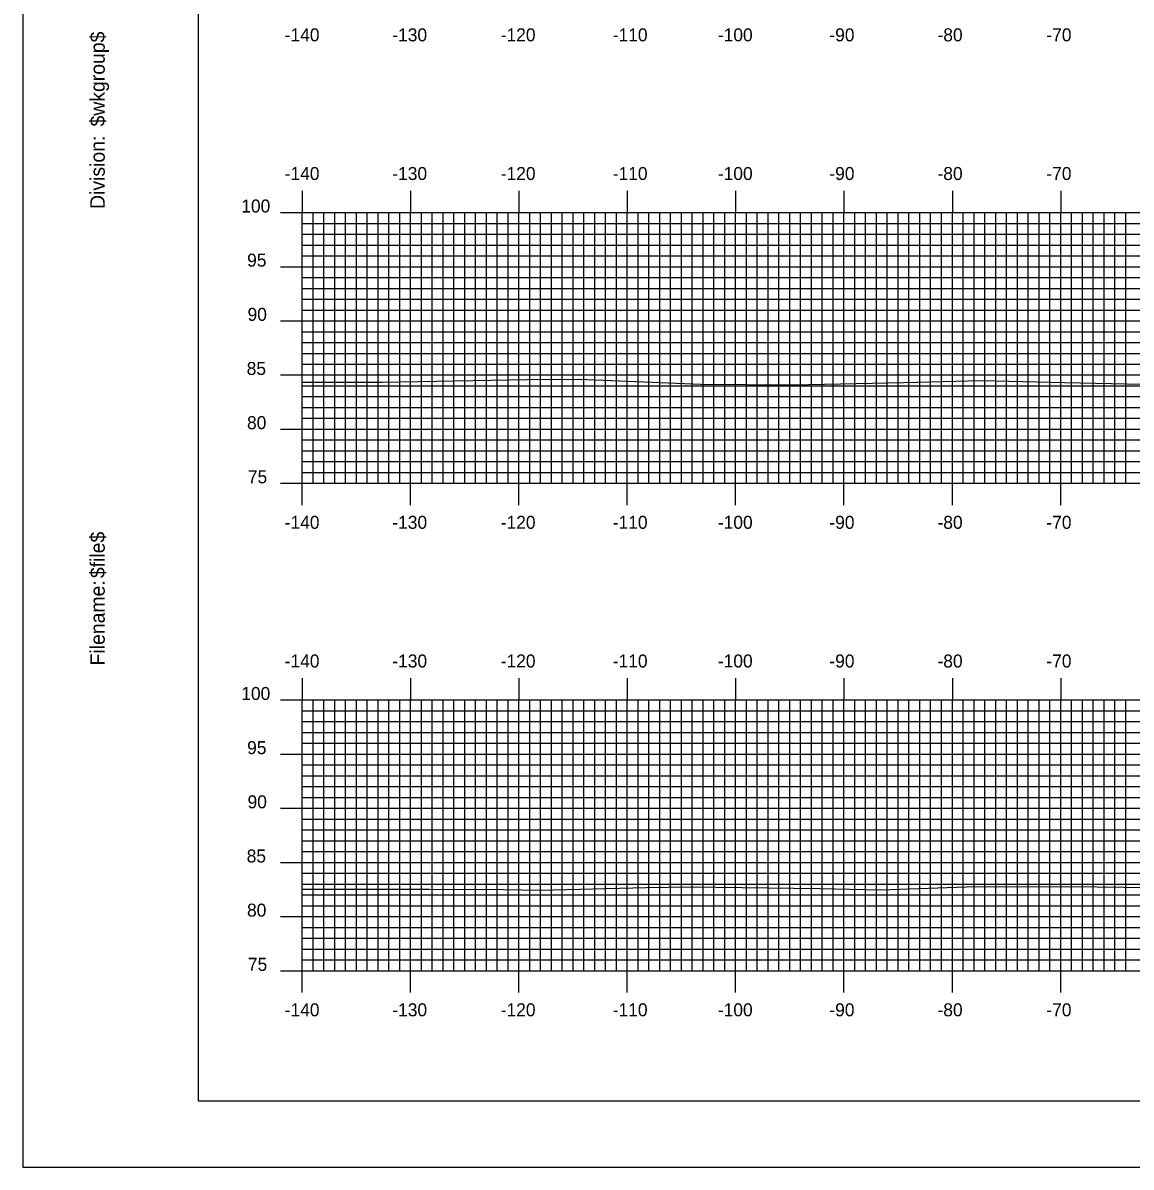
# Model space of a CAD drawing. Extents: x 854116 to 854460, y 364366 to 364586.
# Drawn here: x 854116.4 to 854218.7, y 364365.7 to 364471.3 of the extents above; entities that cross this region are included whole.
import ezdxf

# ---------------------------------------------------------------- set-up
doc = ezdxf.new("R2010")
doc.units = 0
for name, color, linetype in [('BORDER', 7, 'Continuous'), ('H_V ANNOTATION', 7, 'Continuous'), ('MAJOR', 7, 'Continuous'), ('MINOR', 7, 'Continuous'), ('PLOT BOUNDARY', 7, 'Continuous'), ('S_Roadway_Centerline', 7, 'Continuous')]:
    doc.layers.add(name, color=color, linetype=linetype)

msp = doc.modelspace()

# ---------------------------------------------------------------- linework, layer by layer
at = {"layer": 'BORDER'}
msp.add_lwpolyline([(854132.63, 364371.79), (854452.63, 364371.79), (854452.63, 364581.79), (854132.63, 364581.79)], close=True, dxfattribs=at)
at = {"layer": 'MAJOR'}
for p, q in [((854142.23, 364455.79), (854142.23, 364453.79)), ((854152.23, 364455.79), (854152.23, 364453.79)), ((854162.23, 364455.79), (854162.23, 364453.79)), ((854172.23, 364455.79), (854172.23, 364453.79)), ((854182.23, 364455.79), (854182.23, 364453.79)), ((854192.23, 364455.79), (854192.23, 364453.79)), ((854202.23, 364455.79), (854202.23, 364453.79)), ((854212.23, 364455.79), (854212.23, 364453.79)), ((854140.23, 364453.79), (854142.23, 364453.79)), ((854142.23, 364453.79), (854422.23, 364453.79)), ((854142.23, 364428.79), (854142.23, 364453.79)), ((854142.23, 364428.79), (854142.23, 364453.79)), ((854142.23, 364453.79), (854422.23, 364453.79)), ((854152.23, 364428.79), (854152.23, 364453.79)), ((854162.23, 364428.79), (854162.23, 364453.79)), ((854172.23, 364428.79), (854172.23, 364453.79)), ((854182.23, 364428.79), (854182.23, 364453.79)), ((854192.23, 364428.79), (854192.23, 364453.79)), ((854202.23, 364428.79), (854202.23, 364453.79)), ((854212.23, 364428.79), (854212.23, 364453.79)), ((854140.23, 364448.79), (854142.23, 364448.79)), ((854142.23, 364448.79), (854422.23, 364448.79)), ((854140.23, 364443.79), (854142.23, 364443.79)), ((854142.23, 364443.79), (854422.23, 364443.79)), ((854140.23, 364438.79), (854142.23, 364438.79)), ((854142.23, 364438.79), (854422.23, 364438.79)), ((854140.23, 364433.79), (854142.23, 364433.79)), ((854142.23, 364433.79), (854422.23, 364433.79)), ((854140.23, 364428.79), (854142.23, 364428.79)), ((854142.23, 364428.79), (854422.23, 364428.79)), ((854142.23, 364428.79), (854422.23, 364428.79)), ((854142.23, 364426.78), (854142.23, 364428.79)), ((854152.23, 364426.78), (854152.23, 364428.79)), ((854162.23, 364426.78), (854162.23, 364428.79)), ((854172.23, 364426.78), (854172.23, 364428.79)), ((854182.23, 364426.78), (854182.23, 364428.79)), ((854192.23, 364426.78), (854192.23, 364428.79)), ((854202.23, 364426.78), (854202.23, 364428.79)), ((854212.23, 364426.78), (854212.23, 364428.79)), ((854142.23, 364410.79), (854142.23, 364408.79)), ((854152.23, 364410.79), (854152.23, 364408.79)), ((854162.23, 364410.79), (854162.23, 364408.79)), ((854172.23, 364410.79), (854172.23, 364408.79)), ((854182.23, 364410.79), (854182.23, 364408.79)), ((854192.23, 364410.79), (854192.23, 364408.79)), ((854202.23, 364410.79), (854202.23, 364408.79)), ((854212.23, 364410.79), (854212.23, 364408.79)), ((854140.23, 364408.79), (854142.23, 364408.79)), ((854142.23, 364408.79), (854422.23, 364408.79)), ((854142.23, 364383.79), (854142.23, 364408.79)), ((854142.23, 364383.79), (854142.23, 364408.79)), ((854142.23, 364408.79), (854422.23, 364408.79)), ((854152.23, 364383.79), (854152.23, 364408.79)), ((854162.23, 364383.79), (854162.23, 364408.79)), ((854172.23, 364383.79), (854172.23, 364408.79)), ((854182.23, 364383.79), (854182.23, 364408.79)), ((854192.23, 364383.79), (854192.23, 364408.79)), ((854202.23, 364383.79), (854202.23, 364408.79)), ((854212.23, 364383.79), (854212.23, 364408.79)), ((854140.23, 364403.79), (854142.23, 364403.79)), ((854142.23, 364403.79), (854422.23, 364403.79)), ((854140.23, 364398.79), (854142.23, 364398.79)), ((854142.23, 364398.79), (854422.23, 364398.79)), ((854140.23, 364393.79), (854142.23, 364393.79)), ((854142.23, 364393.79), (854422.23, 364393.79)), ((854140.23, 364388.79), (854142.23, 364388.79)), ((854142.23, 364388.79), (854422.23, 364388.79)), ((854140.23, 364383.79), (854142.23, 364383.79)), ((854142.23, 364383.79), (854422.23, 364383.79)), ((854142.23, 364383.79), (854422.23, 364383.79)), ((854142.23, 364381.78), (854142.23, 364383.79)), ((854152.23, 364381.78), (854152.23, 364383.79)), ((854162.23, 364381.78), (854162.23, 364383.79)), ((854172.23, 364381.78), (854172.23, 364383.79)), ((854182.23, 364381.78), (854182.23, 364383.79)), ((854192.23, 364381.78), (854192.23, 364383.79)), ((854202.23, 364381.78), (854202.23, 364383.79)), ((854212.23, 364381.78), (854212.23, 364383.79))]:
    msp.add_line(p, q, dxfattribs=at)
at = {"layer": 'MINOR'}
for p, q in [((854143.23, 364428.79), (854143.23, 364453.79)), ((854144.23, 364428.79), (854144.23, 364453.79)), ((854145.23, 364428.79), (854145.23, 364453.79)), ((854146.23, 364428.79), (854146.23, 364453.79)), ((854147.23, 364428.79), (854147.23, 364453.79)), ((854148.23, 364428.79), (854148.23, 364453.79)), ((854149.23, 364428.79), (854149.23, 364453.79)), ((854150.23, 364428.79), (854150.23, 364453.79)), ((854151.23, 364428.79), (854151.23, 364453.79)), ((854153.23, 364428.79), (854153.23, 364453.79)), ((854154.23, 364428.79), (854154.23, 364453.79)), ((854155.23, 364428.79), (854155.23, 364453.79)), ((854156.23, 364428.79), (854156.23, 364453.79)), ((854157.23, 364428.79), (854157.23, 364453.79)), ((854158.23, 364428.79), (854158.23, 364453.79)), ((854159.23, 364428.79), (854159.23, 364453.79)), ((854160.23, 364428.79), (854160.23, 364453.79)), ((854161.23, 364428.79), (854161.23, 364453.79)), ((854163.23, 364428.79), (854163.23, 364453.79)), ((854164.23, 364428.79), (854164.23, 364453.79)), ((854165.23, 364428.79), (854165.23, 364453.79)), ((854166.23, 364428.79), (854166.23, 364453.79)), ((854167.23, 364428.79), (854167.23, 364453.79)), ((854168.23, 364428.79), (854168.23, 364453.79)), ((854169.23, 364428.79), (854169.23, 364453.79)), ((854170.23, 364428.79), (854170.23, 364453.79)), ((854171.23, 364428.79), (854171.23, 364453.79)), ((854173.23, 364428.79), (854173.23, 364453.79)), ((854174.23, 364428.79), (854174.23, 364453.79)), ((854175.23, 364428.79), (854175.23, 364453.79)), ((854176.23, 364428.79), (854176.23, 364453.79)), ((854177.23, 364428.79), (854177.23, 364453.79)), ((854178.23, 364428.79), (854178.23, 364453.79)), ((854179.23, 364428.79), (854179.23, 364453.79)), ((854180.23, 364428.79), (854180.23, 364453.79)), ((854181.23, 364428.79), (854181.23, 364453.79)), ((854183.23, 364428.79), (854183.23, 364453.79)), ((854184.23, 364428.79), (854184.23, 364453.79)), ((854185.23, 364428.79), (854185.23, 364453.79)), ((854186.23, 364428.79), (854186.23, 364453.79)), ((854187.23, 364428.79), (854187.23, 364453.79)), ((854188.23, 364428.79), (854188.23, 364453.79)), ((854189.23, 364428.79), (854189.23, 364453.79)), ((854190.23, 364428.79), (854190.23, 364453.79)), ((854191.23, 364428.79), (854191.23, 364453.79)), ((854193.23, 364428.79), (854193.23, 364453.79)), ((854194.23, 364428.79), (854194.23, 364453.79)), ((854195.23, 364428.79), (854195.23, 364453.79)), ((854196.23, 364428.79), (854196.23, 364453.79)), ((854197.23, 364428.79), (854197.23, 364453.79)), ((854198.23, 364428.79), (854198.23, 364453.79)), ((854199.23, 364428.79), (854199.23, 364453.79)), ((854200.23, 364428.79), (854200.23, 364453.79)), ((854201.23, 364428.79), (854201.23, 364453.79)), ((854203.23, 364428.79), (854203.23, 364453.79)), ((854204.23, 364428.79), (854204.23, 364453.79)), ((854205.23, 364428.79), (854205.23, 364453.79)), ((854206.23, 364428.79), (854206.23, 364453.79)), ((854207.23, 364428.79), (854207.23, 364453.79)), ((854208.23, 364428.79), (854208.23, 364453.79)), ((854209.23, 364428.79), (854209.23, 364453.79)), ((854210.23, 364428.79), (854210.23, 364453.79)), ((854211.23, 364428.79), (854211.23, 364453.79)), ((854213.23, 364428.79), (854213.23, 364453.79)), ((854214.23, 364428.79), (854214.23, 364453.79)), ((854215.23, 364428.79), (854215.23, 364453.79)), ((854216.23, 364428.79), (854216.23, 364453.79)), ((854217.23, 364428.79), (854217.23, 364453.79)), ((854218.23, 364428.79), (854218.23, 364453.79)), ((854142.23, 364452.79), (854422.23, 364452.79)), ((854142.23, 364452.79), (854144.23, 364452.79)), ((854142.23, 364451.79), (854422.23, 364451.79)), ((854142.23, 364451.79), (854144.23, 364451.79)), ((854142.23, 364450.79), (854422.23, 364450.79)), ((854142.23, 364450.79), (854144.23, 364450.79)), ((854142.23, 364449.79), (854422.23, 364449.79)), ((854142.23, 364449.79), (854144.23, 364449.79)), ((854142.23, 364447.79), (854422.23, 364447.79)), ((854142.23, 364447.79), (854144.23, 364447.79)), ((854142.23, 364446.79), (854422.23, 364446.79)), ((854142.23, 364446.79), (854144.23, 364446.79)), ((854142.23, 364445.79), (854422.23, 364445.79)), ((854142.23, 364445.79), (854144.23, 364445.79)), ((854142.23, 364444.79), (854422.23, 364444.79)), ((854142.23, 364444.79), (854144.23, 364444.79)), ((854142.23, 364442.79), (854422.23, 364442.79)), ((854142.23, 364442.79), (854144.23, 364442.79)), ((854142.23, 364441.79), (854422.23, 364441.79)), ((854142.23, 364441.79), (854144.23, 364441.79)), ((854142.23, 364440.79), (854422.23, 364440.79)), ((854142.23, 364440.79), (854144.23, 364440.79)), ((854142.23, 364439.79), (854422.23, 364439.79)), ((854142.23, 364439.79), (854144.23, 364439.79)), ((854142.23, 364437.79), (854422.23, 364437.79)), ((854142.23, 364437.79), (854144.23, 364437.79)), ((854142.23, 364436.79), (854422.23, 364436.79)), ((854142.23, 364436.79), (854144.23, 364436.79)), ((854142.23, 364435.79), (854422.23, 364435.79)), ((854142.23, 364435.79), (854144.23, 364435.79)), ((854142.23, 364434.79), (854422.23, 364434.79)), ((854142.23, 364434.79), (854144.23, 364434.79)), ((854142.23, 364432.79), (854422.23, 364432.79)), ((854142.23, 364432.79), (854144.23, 364432.79)), ((854142.23, 364431.79), (854422.23, 364431.79)), ((854142.23, 364431.79), (854144.23, 364431.79)), ((854142.23, 364430.79), (854422.23, 364430.79)), ((854142.23, 364430.79), (854144.23, 364430.79)), ((854142.23, 364429.79), (854422.23, 364429.79)), ((854142.23, 364429.79), (854144.23, 364429.79)), ((854143.23, 364383.79), (854143.23, 364408.79)), ((854144.23, 364383.79), (854144.23, 364408.79)), ((854145.23, 364383.79), (854145.23, 364408.79)), ((854146.23, 364383.79), (854146.23, 364408.79)), ((854147.23, 364383.79), (854147.23, 364408.79)), ((854148.23, 364383.79), (854148.23, 364408.79)), ((854149.23, 364383.79), (854149.23, 364408.79)), ((854150.23, 364383.79), (854150.23, 364408.79)), ((854151.23, 364383.79), (854151.23, 364408.79)), ((854153.23, 364383.79), (854153.23, 364408.79)), ((854154.23, 364383.79), (854154.23, 364408.79)), ((854155.23, 364383.79), (854155.23, 364408.79)), ((854156.23, 364383.79), (854156.23, 364408.79)), ((854157.23, 364383.79), (854157.23, 364408.79)), ((854158.23, 364383.79), (854158.23, 364408.79)), ((854159.23, 364383.79), (854159.23, 364408.79)), ((854160.23, 364383.79), (854160.23, 364408.79)), ((854161.23, 364383.79), (854161.23, 364408.79)), ((854163.23, 364383.79), (854163.23, 364408.79)), ((854164.23, 364383.79), (854164.23, 364408.79)), ((854165.23, 364383.79), (854165.23, 364408.79)), ((854166.23, 364383.79), (854166.23, 364408.79)), ((854167.23, 364383.79), (854167.23, 364408.79)), ((854168.23, 364383.79), (854168.23, 364408.79)), ((854169.23, 364383.79), (854169.23, 364408.79)), ((854170.23, 364383.79), (854170.23, 364408.79)), ((854171.23, 364383.79), (854171.23, 364408.79)), ((854173.23, 364383.79), (854173.23, 364408.79)), ((854174.23, 364383.79), (854174.23, 364408.79)), ((854175.23, 364383.79), (854175.23, 364408.79)), ((854176.23, 364383.79), (854176.23, 364408.79)), ((854177.23, 364383.79), (854177.23, 364408.79)), ((854178.23, 364383.79), (854178.23, 364408.79)), ((854179.23, 364383.79), (854179.23, 364408.79)), ((854180.23, 364383.79), (854180.23, 364408.79)), ((854181.23, 364383.79), (854181.23, 364408.79)), ((854183.23, 364383.79), (854183.23, 364408.79)), ((854184.23, 364383.79), (854184.23, 364408.79)), ((854185.23, 364383.79), (854185.23, 364408.79)), ((854186.23, 364383.79), (854186.23, 364408.79)), ((854187.23, 364383.79), (854187.23, 364408.79)), ((854188.23, 364383.79), (854188.23, 364408.79)), ((854189.23, 364383.79), (854189.23, 364408.79)), ((854190.23, 364383.79), (854190.23, 364408.79)), ((854191.23, 364383.79), (854191.23, 364408.79)), ((854193.23, 364383.79), (854193.23, 364408.79)), ((854194.23, 364383.79), (854194.23, 364408.79)), ((854195.23, 364383.79), (854195.23, 364408.79)), ((854196.23, 364383.79), (854196.23, 364408.79)), ((854197.23, 364383.79), (854197.23, 364408.79)), ((854198.23, 364383.79), (854198.23, 364408.79)), ((854199.23, 364383.79), (854199.23, 364408.79)), ((854200.23, 364383.79), (854200.23, 364408.79)), ((854201.23, 364383.79), (854201.23, 364408.79)), ((854203.23, 364383.79), (854203.23, 364408.79)), ((854204.23, 364383.79), (854204.23, 364408.79)), ((854205.23, 364383.79), (854205.23, 364408.79)), ((854206.23, 364383.79), (854206.23, 364408.79)), ((854207.23, 364383.79), (854207.23, 364408.79)), ((854208.23, 364383.79), (854208.23, 364408.79)), ((854209.23, 364383.79), (854209.23, 364408.79)), ((854210.23, 364383.79), (854210.23, 364408.79)), ((854211.23, 364383.79), (854211.23, 364408.79)), ((854213.23, 364383.79), (854213.23, 364408.79)), ((854214.23, 364383.79), (854214.23, 364408.79)), ((854215.23, 364383.79), (854215.23, 364408.79)), ((854216.23, 364383.79), (854216.23, 364408.79)), ((854217.23, 364383.79), (854217.23, 364408.79)), ((854218.23, 364383.79), (854218.23, 364408.79)), ((854142.23, 364407.79), (854422.23, 364407.79)), ((854142.23, 364407.79), (854144.23, 364407.79)), ((854142.23, 364406.79), (854422.23, 364406.79)), ((854142.23, 364406.79), (854144.23, 364406.79)), ((854142.23, 364405.79), (854422.23, 364405.79)), ((854142.23, 364405.79), (854144.23, 364405.79)), ((854142.23, 364404.79), (854422.23, 364404.79)), ((854142.23, 364404.79), (854144.23, 364404.79)), ((854142.23, 364402.79), (854422.23, 364402.79)), ((854142.23, 364402.79), (854144.23, 364402.79)), ((854142.23, 364401.79), (854422.23, 364401.79)), ((854142.23, 364401.79), (854144.23, 364401.79)), ((854142.23, 364400.79), (854422.23, 364400.79)), ((854142.23, 364400.79), (854144.23, 364400.79)), ((854142.23, 364399.79), (854422.23, 364399.79)), ((854142.23, 364399.79), (854144.23, 364399.79)), ((854142.23, 364397.79), (854422.23, 364397.79)), ((854142.23, 364397.79), (854144.23, 364397.79)), ((854142.23, 364396.79), (854422.23, 364396.79)), ((854142.23, 364396.79), (854144.23, 364396.79)), ((854142.23, 364395.79), (854422.23, 364395.79)), ((854142.23, 364395.79), (854144.23, 364395.79)), ((854142.23, 364394.79), (854422.23, 364394.79)), ((854142.23, 364394.79), (854144.23, 364394.79)), ((854142.23, 364392.79), (854422.23, 364392.79)), ((854142.23, 364392.79), (854144.23, 364392.79)), ((854142.23, 364391.79), (854422.23, 364391.79)), ((854142.23, 364391.79), (854144.23, 364391.79)), ((854142.23, 364390.79), (854422.23, 364390.79)), ((854142.23, 364390.79), (854144.23, 364390.79)), ((854142.23, 364389.79), (854422.23, 364389.79)), ((854142.23, 364389.79), (854144.23, 364389.79)), ((854142.23, 364387.79), (854422.23, 364387.79)), ((854142.23, 364387.79), (854144.23, 364387.79)), ((854142.23, 364386.79), (854422.23, 364386.79)), ((854142.23, 364386.79), (854144.23, 364386.79)), ((854142.23, 364385.79), (854422.23, 364385.79)), ((854142.23, 364385.79), (854144.23, 364385.79)), ((854142.23, 364384.79), (854422.23, 364384.79)), ((854142.23, 364384.79), (854144.23, 364384.79))]:
    msp.add_line(p, q, dxfattribs=at)
at = {"layer": 'PLOT BOUNDARY'}
msp.add_lwpolyline([(854116.44, 364365.67), (854456.44, 364365.67), (854456.44, 364585.67), (854116.44, 364585.67)], close=True, dxfattribs=at)
at = {"layer": 'S_Roadway_Centerline'}
for points in [[(854142.23, 364438.14), (854149.59, 364438.12), (854163.01, 364438.36), (854167.75, 364438.39), (854179.01, 364437.95), (854187.52, 364437.87), (854197.74, 364438.11), (854204.89, 364438.28), (854212.58, 364438.11), (854222.7, 364437.89)], [(854142.23, 364391.34), (854143.86, 364391.33), (854153.94, 364391.34), (854160.82, 364391.29), (854164.16, 364391.24), (854173.96, 364391.47), (854178.02, 364391.53), (854190, 364391.39), (854195.64, 364391.26), (854203.52, 364391.53), (854213.12, 364391.56), (854223.01, 364391.45)]]:
    msp.add_lwpolyline(points, dxfattribs=at)

# ---------------------------------------------------------------- texts
at = {"layer": 'BORDER'}
for s, p in [('$wkgroup$', (854124, 364461.73)), ('Division:', (854124, 364454.12)), ('$file$', (854124, 364420.04)), ('Filename:', (854124, 364411.98))]:
    msp.add_text(s, height=1.339, rotation=90, dxfattribs=at).set_placement(p)
at = {"layer": 'H_V ANNOTATION'}
for s, p in [('-140', (854140.61, 364469.59)), ('-130', (854150.54, 364469.59)), ('-120', (854160.55, 364469.59)), ('-110', (854170.89, 364469.59)), ('-100', (854180.59, 364469.59)), ('-90', (854190.88, 364469.59)), ('-80', (854200.86, 364469.59)), ('-70', (854210.91, 364469.59)), ('-140', (854140.61, 364456.79)), ('-130', (854150.54, 364456.79)), ('-120', (854160.55, 364456.79)), ('-110', (854170.89, 364456.79)), ('-100', (854180.59, 364456.79)), ('-90', (854190.88, 364456.79)), ('-80', (854200.86, 364456.79)), ('-70', (854210.91, 364456.79)), ('100', (854136.6, 364453.79)), ('95', (854137.14, 364448.79)), ('90', (854137.18, 364443.79)), ('85', (854137.1, 364438.79)), ('80', (854137.13, 364433.79)), ('75', (854137.21, 364428.79)), ('-140', (854140.61, 364424.59)), ('-130', (854150.54, 364424.59)), ('-120', (854160.55, 364424.59)), ('-110', (854170.89, 364424.59)), ('-100', (854180.59, 364424.59)), ('-90', (854190.88, 364424.59)), ('-80', (854200.86, 364424.59)), ('-70', (854210.91, 364424.59)), ('-140', (854140.61, 364411.79)), ('-130', (854150.54, 364411.79)), ('-120', (854160.55, 364411.79)), ('-110', (854170.89, 364411.79)), ('-100', (854180.59, 364411.79)), ('-90', (854190.88, 364411.79)), ('-80', (854200.86, 364411.79)), ('-70', (854210.91, 364411.79)), ('100', (854136.6, 364408.79)), ('95', (854137.14, 364403.79)), ('90', (854137.18, 364398.79)), ('85', (854137.1, 364393.79)), ('80', (854137.13, 364388.79)), ('75', (854137.21, 364383.79)), ('-140', (854140.61, 364379.59)), ('-130', (854150.54, 364379.59)), ('-120', (854160.55, 364379.59)), ('-110', (854170.89, 364379.59)), ('-100', (854180.59, 364379.59)), ('-90', (854190.88, 364379.59)), ('-80', (854200.86, 364379.59)), ('-70', (854210.91, 364379.59))]:
    msp.add_text(s, height=1.2, dxfattribs=at).set_placement(p)
at = {"layer": 'MAJOR'}
for p in [(854142.22, 364428.79), (854142.22, 364383.79)]:
    msp.add_text('-', height=0.012, dxfattribs=at).set_placement(p)

doc.saveas('drawing.dxf')
